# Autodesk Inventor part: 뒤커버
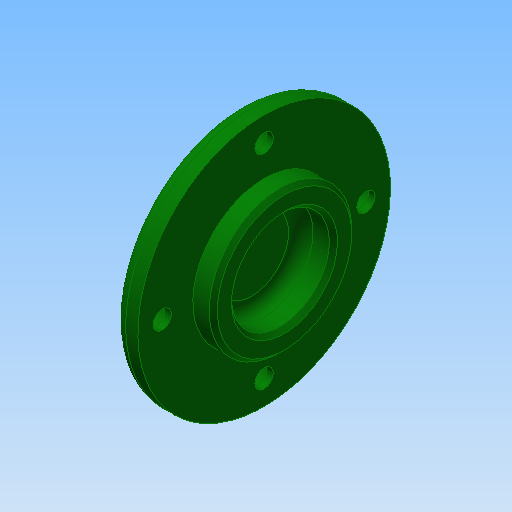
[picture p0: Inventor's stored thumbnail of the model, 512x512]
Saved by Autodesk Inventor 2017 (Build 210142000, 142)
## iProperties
Created: 2015-12
Part Number: 뒤커버
Document SubType Name: Modeling
Designer: mdu
Density: 2.71 g/cm^3
Material: 알루미늄 6061
Appearance: 진녹색
Mass: 56.1988 g
Surface Area: 84.0425 cm^2
Volume: 20.7376 cm^3
Author: mdu
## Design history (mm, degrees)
sketch "스케치1"
  geometry: L1 (-7, 0)-(7, 0); L2 (-7, 0)-(-7, 15.539); L3 (-7, 15.539)-(-4, 18.5); L4 (-4, 18.5)-(-4, 31); L5 (-4, 31)-(2, 31); L6 (2, 31)-(2, 17.5); L7 (2, 17.5)-(7, 17.5); L8 (7, 17.5)-(7, 0); 2 further points
  constraints: 16 end point, 4 parallel, 2 perpendicular, 1 coincident, 1 horizontal, 1 midpoint
  dimensions: "d0" = 14 distance of L1.start L1.end; "d1" = 62 diameter of L5 L1; "d2" = 35 diameter of L7 L1; "d3" = 37 diameter of L3.end L1; "d4" = 3 distance between parallel lines of L4 L2; "d5" = 6 distance of L4.end L5.end
revolve "회전1" sketch "스케치1" stored, may be unused: angle "d6" = 90 deg
sketch "스케치2" dims "d32" = 50
  geometry: 3 further points
  constraints: 2 vertical alignment, 1 coincident, 2 other
hole "구멍1" sketch "스케치2" at (0, 25) diameter "d8" = 4.5; stored, may be unused: countersink angle "d12" = 90 deg, drill point angle "d14" = 118 deg; dims "d9" = 6, "d10" = 8, "d11" = 4.4, "d13" = 8
hole "구멍2" diameter "d20" = 24; stored, may be unused: countersink angle "d24" = 90 deg, drill point angle "d26" = 0 deg; dims "d18" = 10, "d19" = 10, "d21" = 6, "d22" = 8, "d23" = 4.4, "d25" = 8
fillet "모깎기1" dims "d27" = 3
fillet "모깎기2" dims "d28" = 3
chamfer "모따기1" distance "d29" = 1; stored, may be unused: second distance "d30" = 2, angle "d31" = 45 deg
node "솔리드1"
pattern_circular "원형 패턴1" dims angle "d16" = 360 deg
